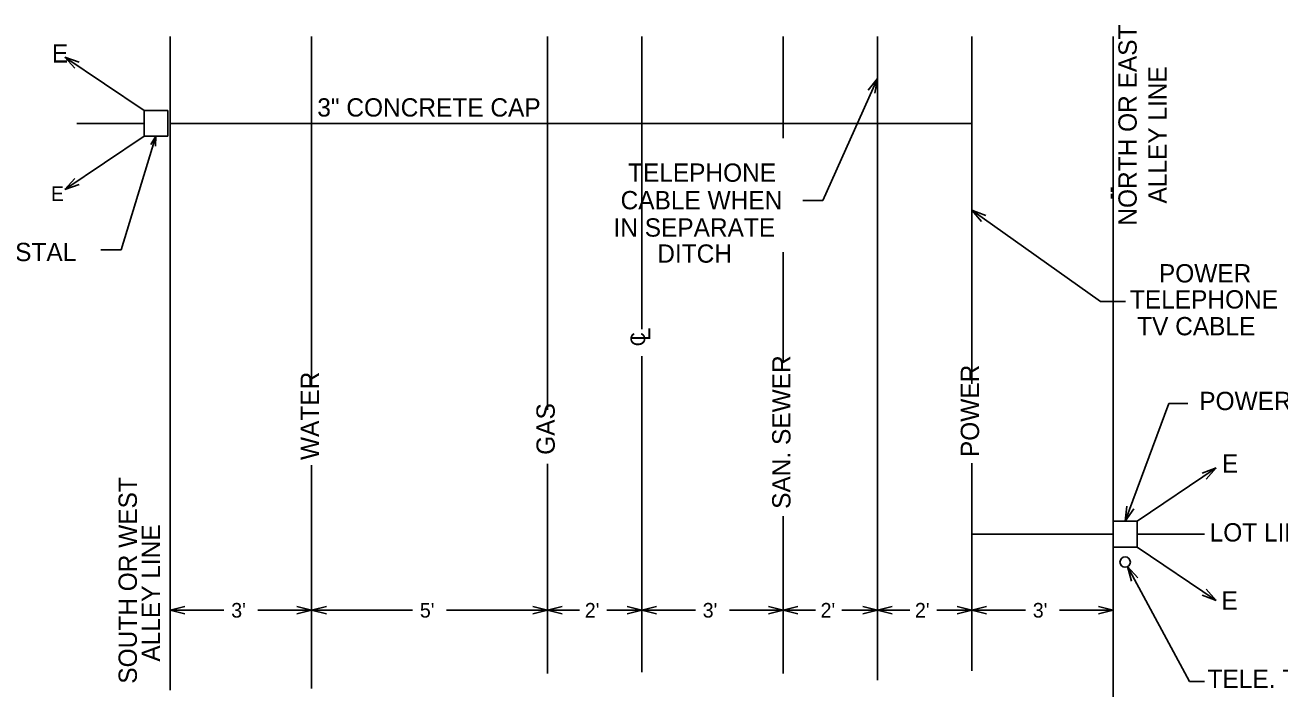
# Model space of a CAD drawing. Extents: x 524397 to 525117, y 3701341 to 3701821.
# Drawn here: x 524465.7 to 524603, y 3701527.1 to 3701600.6 of the extents above; entities that cross this region are included whole.
import ezdxf

# ---------------------------------------------------------------- set-up
doc = ezdxf.new("R2010")
doc.units = 0
doc.layers.add('Level 1', color=7, linetype='Continuous')
doc.layers.add('Level 11', color=7, linetype='Continuous')

msp = doc.modelspace()

# ---------------------------------------------------------------- linework, layer by layer
at = {"layer": 'Level 1'}
for p, q in [((524481.61, 3701599.3), (524481.61, 3701527.84)), ((524497.07, 3701599.3), (524497.07, 3701561.02)), ((524522.86, 3701599.3), (524522.86, 3701558.47)), ((524533.17, 3701599.3), (524533.17, 3701567.31)), ((524548.64, 3701599.3), (524548.64, 3701588.2)), ((524558.95, 3701599.3), (524558.95, 3701528.9)), ((524569.26, 3701599.3), (524569.26, 3701561.34)), ((524584.73, 3701599.3), (524584.73, 3701527.09)), ((524478.74, 3701591.23), (524481.36, 3701591.23)), ((524478.74, 3701588.39), (524478.74, 3701591.23)), ((524481.36, 3701591.23), (524481.36, 3701588.39)), ((524478.74, 3701589.81), (524471.38, 3701589.81)), ((524481.61, 3701589.81), (524569.26, 3701589.81)), ((524480.05, 3701588.39), (524476.25, 3701575.97)), ((524481.36, 3701588.39), (524478.74, 3701588.39)), ((524479.5, 3701587.48), (524480.05, 3701588.39)), ((524480.05, 3701588.39), (524479.99, 3701587.33)), ((524476.25, 3701575.97), (524474.02, 3701575.97)), ((524548.64, 3701575.71), (524548.64, 3701563.62)), ((524533.17, 3701564.35), (524533.17, 3701529.8)), ((524497.07, 3701552.44), (524497.07, 3701527.99)), ((524522.86, 3701552.57), (524522.86, 3701529.65)), ((524569.26, 3701552.64), (524569.26, 3701529.95)), ((524548.64, 3701546.85), (524548.64, 3701529.65)), ((524584.73, 3701543.46), (524584.73, 3701546.3)), ((524584.73, 3701546.3), (524587.35, 3701546.3)), ((524587.35, 3701546.3), (524587.35, 3701543.46)), ((524569.26, 3701544.88), (524584.73, 3701544.88)), ((524587.35, 3701544.88), (524594.71, 3701544.88)), ((524587.35, 3701543.46), (524584.73, 3701543.46))]:
    msp.add_line(p, q, dxfattribs=at)
msp.add_circle((524586.04, 3701541.83), 0.571, dxfattribs=at)
at = {"layer": 'Level 11'}
for p, q in [((524470.09, 3701597.05), (524478.74, 3701591.23)), ((524471.19, 3701595.83), (524470.09, 3701597.05)), ((524470.09, 3701597.05), (524471.64, 3701596.49)), ((524558.95, 3701594.72), (524552.97, 3701581.36)), ((524557.93, 3701593.42), (524558.95, 3701594.72)), ((524558.95, 3701594.72), (524558.66, 3701593.1)), ((524470.09, 3701582.57), (524478.74, 3701588.39)), ((524470.09, 3701582.57), (524471.19, 3701583.79)), ((524471.64, 3701583.13), (524470.09, 3701582.57)), ((524552.97, 3701581.36), (524550.8, 3701581.36)), ((524570.34, 3701579.07), (524569.26, 3701580.32)), ((524569.26, 3701580.32), (524570.8, 3701579.72)), ((524569.26, 3701580.32), (524583.34, 3701570.33)), ((524583.34, 3701570.33), (524586.08, 3701570.33)), ((524586.04, 3701546.3), (524590.83, 3701559.17)), ((524590.83, 3701559.17), (524592.91, 3701559.17)), ((524596, 3701552.12), (524587.35, 3701546.3)), ((524594.45, 3701551.56), (524596, 3701552.12)), ((524596, 3701552.12), (524594.9, 3701550.89)), ((524586.04, 3701546.3), (524586.23, 3701547.94)), ((524586.98, 3701547.66), (524586.04, 3701546.3)), ((524596, 3701537.63), (524587.35, 3701543.46)), ((524586.72, 3701539.73), (524586.31, 3701541.33)), ((524586.31, 3701541.33), (524587.42, 3701540.11)), ((524586.31, 3701541.33), (524593.09, 3701528.78)), ((524594.9, 3701538.86), (524596, 3701537.63)), ((524596, 3701537.63), (524594.45, 3701538.2)), ((524481.61, 3701536.56), (524483.21, 3701536.96)), ((524487.48, 3701536.56), (524481.61, 3701536.56)), ((524483.21, 3701536.16), (524481.61, 3701536.56)), ((524491.2, 3701536.56), (524497.07, 3701536.56)), ((524495.47, 3701536.96), (524497.07, 3701536.56)), ((524497.07, 3701536.56), (524495.47, 3701536.16)), ((524497.07, 3701536.56), (524498.68, 3701536.96)), ((524508.11, 3701536.56), (524497.07, 3701536.56)), ((524498.68, 3701536.16), (524497.07, 3701536.56)), ((524511.82, 3701536.56), (524522.86, 3701536.56)), ((524517.25, 3701536.56), (524522.86, 3701536.56)), ((524521.25, 3701536.96), (524522.86, 3701536.56)), ((524521.25, 3701536.96), (524522.86, 3701536.56)), ((524522.86, 3701536.56), (524521.25, 3701536.16)), ((524522.86, 3701536.56), (524521.25, 3701536.16)), ((524522.86, 3701536.56), (524524.46, 3701536.96)), ((524522.86, 3701536.56), (524526.36, 3701536.56)), ((524524.46, 3701536.16), (524522.86, 3701536.56)), ((524533.17, 3701536.56), (524529.36, 3701536.56)), ((524531.57, 3701536.96), (524533.17, 3701536.56)), ((524533.17, 3701536.56), (524531.57, 3701536.16)), ((524533.17, 3701536.56), (524534.77, 3701536.96)), ((524533.17, 3701536.56), (524534.77, 3701536.96)), ((524538.77, 3701536.56), (524533.17, 3701536.56)), ((524539.04, 3701536.56), (524533.17, 3701536.56)), ((524534.77, 3701536.16), (524533.17, 3701536.56)), ((524534.77, 3701536.16), (524533.17, 3701536.56)), ((524542.76, 3701536.56), (524548.64, 3701536.56)), ((524543.03, 3701536.56), (524548.64, 3701536.56)), ((524547.04, 3701536.96), (524548.64, 3701536.56)), ((524547.04, 3701536.96), (524548.64, 3701536.56)), ((524548.64, 3701536.56), (524547.04, 3701536.16)), ((524548.64, 3701536.56), (524547.04, 3701536.16)), ((524548.64, 3701536.56), (524550.24, 3701536.96)), ((524548.64, 3701536.56), (524552.18, 3701536.56)), ((524550.24, 3701536.16), (524548.64, 3701536.56)), ((524555.05, 3701536.56), (524558.95, 3701536.56)), ((524557.35, 3701536.96), (524558.95, 3701536.56)), ((524558.95, 3701536.56), (524557.35, 3701536.16)), ((524558.95, 3701536.56), (524560.55, 3701536.96)), ((524562.51, 3701536.56), (524558.95, 3701536.56)), ((524560.55, 3701536.16), (524558.95, 3701536.56)), ((524569.26, 3701536.56), (524565.43, 3701536.56)), ((524567.66, 3701536.96), (524569.26, 3701536.56)), ((524569.26, 3701536.56), (524567.66, 3701536.16)), ((524569.26, 3701536.56), (524570.86, 3701536.96)), ((524569.26, 3701536.56), (524570.86, 3701536.96)), ((524574.87, 3701536.56), (524569.26, 3701536.56)), ((524575.14, 3701536.56), (524569.26, 3701536.56)), ((524570.86, 3701536.16), (524569.26, 3701536.56)), ((524570.86, 3701536.16), (524569.26, 3701536.56)), ((524578.86, 3701536.56), (524584.73, 3701536.56)), ((524583.13, 3701536.96), (524584.73, 3701536.56)), ((524584.73, 3701536.56), (524583.13, 3701536.16)), ((524593.09, 3701528.78), (524594.7, 3701528.78))]:
    msp.add_line(p, q, dxfattribs=at)

# ---------------------------------------------------------------- texts
at = {"layer": 'Level 1'}
for s, height, p in [('E', 2, (524468.66, 3701596.46)), ('E', 1.6, (524468.56, 3701581.32)), ('E', 2, (524596.62, 3701551.61)), ('LOT LINE', 2, (524595.28, 3701544.08)), ('E', 2, (524596.57, 3701536.63))]:
    msp.add_text(s, height=height, dxfattribs=at).set_placement(p)
for s, height, rotation, p in [('--', 1.601, 270, (524583.93, 3701582.91)), ('C', 1.6, 90, (524533.55, 3701565.43)), ('L', 2, 90, (524534.1, 3701565.99))]:
    msp.add_text(s, height=height, rotation=rotation, dxfattribs=at).set_placement(p)
at = {"layer": 'Level 11'}
for s, p in [('NORTH OR EAST', (524587.3, 3701578.62)), ('ALLEY LINE', (524590.57, 3701581.04)), ('SAN. SEWER', (524549.44, 3701547.65)), ('WATER', (524497.87, 3701552.99)), ('POWER', (524570.06, 3701553.31)), ('GAS', (524523.66, 3701553.56)), ('SOUTH OR WEST', (524477.96, 3701528.53)), ('ALLEY LINE', (524480.5, 3701530.94))]:
    msp.add_text(s, height=2, rotation=90, dxfattribs=at).set_placement(p)
for s, height, p in [('3" CONCRETE CAP', 2, (524497.69, 3701590.55)), ('TELEPHONE', 2, (524531.67, 3701583.42)), ('CABLE WHEN', 2, (524530.86, 3701580.41)), ('IN SEPARATE', 2, (524530.08, 3701577.42)), ('POWER PEDESTAL', 2, (524446.52, 3701574.74)), ('DITCH', 2, (524534.87, 3701574.57)), ('POWER', 2, (524589.73, 3701572.41)), ('TELEPHONE', 2, (524586.56, 3701569.56)), ('TV CABLE', 2, (524587.35, 3701566.63)), ('POWER PEDESTAL', 2, (524594.14, 3701558.45)), ("3'", 1.601, (524488.28, 3701535.76)), ("5'", 1.601, (524508.91, 3701535.76)), ("2'", 1.601, (524526.95, 3701535.76)), ("3'", 1.601, (524539.84, 3701535.76)), ("2'", 1.601, (524552.73, 3701535.76)), ("2'", 1.601, (524563.05, 3701535.76)), ("3'", 1.601, (524575.94, 3701535.76)), ('TELE. TERM', 2, (524595.05, 3701528.06))]:
    msp.add_text(s, height=height, dxfattribs=at).set_placement(p)

doc.saveas('drawing.dxf')
